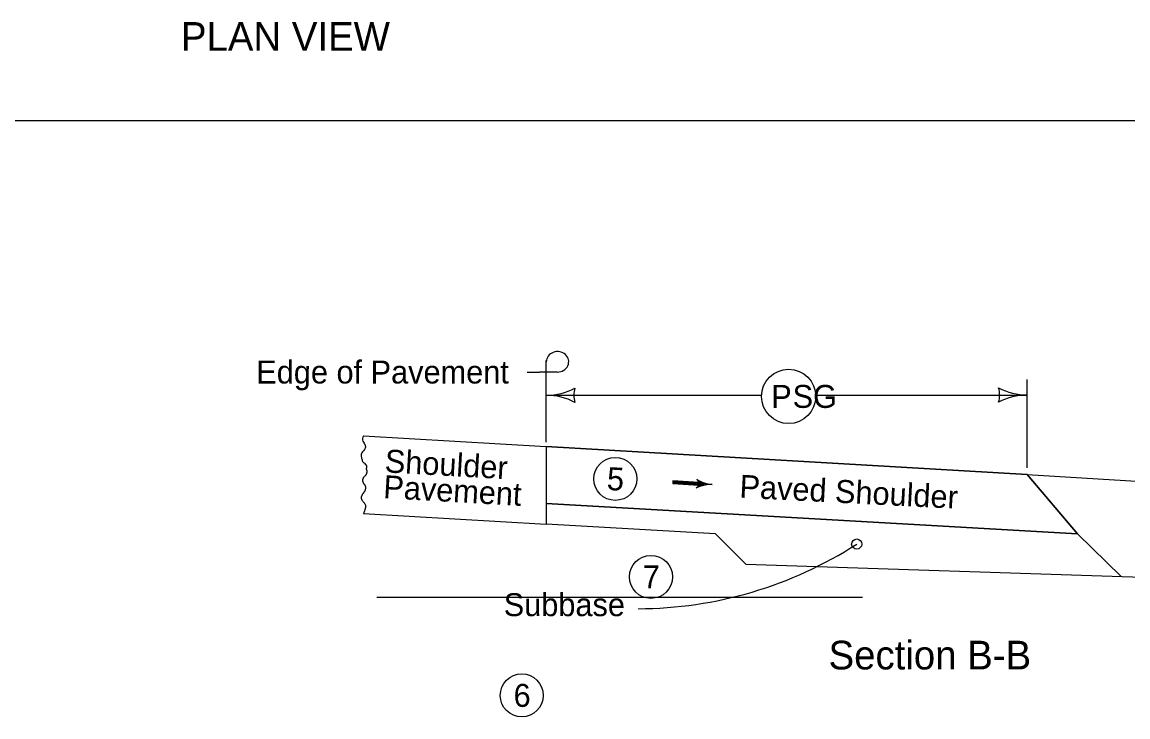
# Model space of a CAD drawing. Extents: x 10038 to 81668, y 7924 to 11018.
# Drawn here: x 11041 to 11812, y 8943 to 9428 of the extents above; entities that cross this region are included whole.
import ezdxf

# ---------------------------------------------------------------- set-up
doc = ezdxf.new("R2010")
doc.units = 0
for name, color, linetype in [('DsnShtMinorGrid05', 7, 'Continuous'), ('DsnShtMinorGrid09', 7, 'Continuous'), ('DsnShtMinorGrid10', 7, 'Continuous'), ('DsnShtMinorGrid11', 7, 'Continuous'), ('DsnShtMinorGrid14', 7, 'Continuous'), ('Level 60', 7, 'Continuous')]:
    doc.layers.add(name, color=color, linetype=linetype)

msp = doc.modelspace()

# ---------------------------------------------------------------- linework, layer by layer
at = {"layer": 'DsnShtMinorGrid05'}
for p, q in [((11742.05, 9116.81), (11742.05, 9178.49)), ((11406.83, 9167.5), (11556.83, 9167.5)), ((11594.65, 9167.65), (11742.05, 9167.65))]:
    msp.add_line(p, q, dxfattribs=at)
msp.add_circle((11575.74, 9166.68), 18.93, dxfattribs=at)
for centre, radius, start, end in [((11406.83, 9210), 42.5, 270, 298.07249), ((11442.47, 9167.5), 16.42, 162.26665, 197.73335), ((11706.41, 9167.65), 16.42, 342.26665, 17.73335), ((11742.05, 9210.15), 42.5, 241.92751, 270), ((11406.83, 9125), 42.5, 61.92751, 90), ((11742.05, 9125.15), 42.5, 90, 118.07249), ((11470.24, 9300.72), 282.03, 270.13198, 302.84273)]:
    msp.add_arc(centre, radius, start, end, dxfattribs=at)
at = {"layer": 'DsnShtMinorGrid09'}
for centre in [(11454.95, 9109.17), (11479.8, 9040.88), (11389.74, 8958.27)]:
    msp.add_circle(centre, 15, dxfattribs=at)
at = {"layer": 'DsnShtMinorGrid10'}
for p, q in [((11406.83, 9170.82), (11406.83, 9191.68)), ((11393.46, 9183.67), (11402.14, 9183.67)), ((11414.64, 9183.67), (11402.14, 9183.67)), ((11406.83, 9134.88), (11406.83, 9170.82)), ((11513.21, 9105.78), (11495.01, 9106.83)), ((11513.11, 9104.84), (11513.11, 9104.84)), ((11513.23, 9106.79), (11513.23, 9106.79))]:
    msp.add_line(p, q, dxfattribs=at)
for points in [[(11513.24, 9106.72), (11495.07, 9107.77), (11494.94, 9105.89), (11513.11, 9104.84), (11513.16, 9106.45), (11495.29, 9107.55), (11495.24, 9106.05), (11512.73, 9105.1), (11512.85, 9106.22), (11495.53, 9107.28), (11495.5, 9106.28), (11512.51, 9105.3), (11512.61, 9106.01), (11495.72, 9107.06), (11495.7, 9106.5), (11512.3, 9105.56)], [(11512.84, 9107.97), (11513.53, 9106.81), (11513.51, 9105.16), (11512.75, 9103.76), (11515.5, 9104.63), (11518.7, 9105.28), (11519.6, 9105.42), (11517.35, 9105.96), (11514.13, 9107.19), (11513.18, 9107.73), (11513.31, 9104.21), (11518.25, 9105.43), (11513.61, 9107.01), (11513.63, 9104.59), (11517.03, 9105.52), (11514.03, 9106.38), (11513.79, 9105), (11515.95, 9105.5), (11514.37, 9106.01), (11514.23, 9105.35), (11515.02, 9105.51)]]:
    msp.add_lwpolyline(points, dxfattribs=at)
for centre, major_axis, start_param, end_param in [((11414.64, 9190.8), (-7.81, 0), 1.570796, 6.283185), ((11509.44, 9105.99), (3.88, 0), 5.202895, 7.237436), ((11521.72, 9085), (22.17, 0), 1.537172, 2.061295), ((11524.51, 9125.42), (-22.17, 0), 0.954258, 1.478381)]:
    msp.add_ellipse(centre, major_axis=major_axis, ratio=0.913811, start_param=start_param, end_param=end_param, dxfattribs=at)
at = {"layer": 'DsnShtMinorGrid11'}
msp.add_line((12305.9, 9358.71), (10150.33, 9358.71), dxfattribs=at)
at = {"layer": 'DsnShtMinorGrid14'}
msp.add_circle((11623.19, 9063.77), 3.54, dxfattribs=at)
at = {"layer": 'Level 60'}
for p, q in [((11279.36, 9139.15), (11406.83, 9131.74)), ((11406.83, 9131.74), (11406.83, 9077.73)), ((11406.83, 9131.74), (11741.97, 9112.25)), ((11741.97, 9112.25), (11406.83, 9131.74)), ((11406.83, 9131.74), (11406.83, 9092.14)), ((11741.97, 9112.25), (11777.01, 9070.8)), ((11741.97, 9112.25), (11876.8, 9103.86)), ((11777.01, 9070.8), (11741.97, 9112.25)), ((11777.01, 9070.8), (11406.83, 9092.14)), ((11406.83, 9092.14), (11777.01, 9070.8)), ((11279.4, 9085.14), (11406.83, 9077.73)), ((11524.67, 9070.93), (11406.83, 9077.73)), ((11524.67, 9070.93), (11546.01, 9049.72)), ((11777.01, 9070.8), (11807.53, 9041.17)), ((11546.01, 9049.72), (12029.35, 9033.93)), ((11288.78, 9026.82), (11627.28, 9026.82))]:
    msp.add_line(p, q, dxfattribs=at)
msp.add_circle((11454.95, 9109.17), 15, dxfattribs=at)
for points in [[(11279.36, 9139.15), (11278.86, 9135.55), (11279.9, 9134.04), (11280.77, 9131.75), (11280.16, 9129.69), (11278.26, 9127.31), (11277.74, 9125.41), (11278.26, 9123.12), (11279.12, 9120.74), (11280.16, 9120.03), (11281.55, 9117.49), (11281.54, 9116.65)], [(11279.58, 9099.54), (11279.79, 9099.79), (11279.99, 9100.05), (11280.34, 9100.61), (11280.62, 9101.2), (11280.73, 9101.51), (11280.83, 9101.82), (11280.97, 9102.44), (11281.02, 9103.06), (11280.97, 9103.65), (11280.91, 9103.93), (11280.87, 9104.06), (11280.83, 9104.19), (11280.62, 9104.57), (11280.33, 9104.93), (11280.04, 9105.3), (11279.79, 9105.7), (11279.65, 9105.98), (11279.51, 9106.26), (11279.25, 9106.84), (11279.05, 9107.4), (11278.97, 9107.7), (11278.92, 9107.99), (11278.91, 9108.12), (11278.91, 9108.25), (11279.06, 9109.02), (11279.27, 9109.54), (11279.53, 9110.05), (11279.97, 9110.69), (11280.49, 9111.23), (11281, 9111.78), (11281.23, 9112.09), (11281.43, 9112.43), (11281.64, 9112.9), (11281.8, 9113.38), (11281.9, 9113.85), (11281.93, 9114.09), (11281.94, 9114.21), (11281.95, 9114.33), (11281.91, 9114.84), (11281.76, 9115.35), (11281.71, 9115.48), (11281.65, 9115.6), (11281.6, 9115.73), (11281.58, 9115.86), (11281.54, 9116.65)], [(11279.58, 9099.54), (11279.36, 9099.31), (11279.11, 9099.07), (11278.88, 9098.83), (11278.7, 9098.56), (11278.56, 9098.28), (11278.42, 9097.99), (11278.16, 9097.42), (11278.04, 9097.14), (11277.95, 9096.85), (11277.88, 9096.56), (11277.85, 9096.41), (11277.83, 9096.26), (11277.84, 9095.75), (11277.97, 9095.23), (11278.18, 9094.71), (11278.44, 9094.2), (11278.88, 9093.57), (11279.4, 9093.02), (11279.91, 9092.47), (11280.14, 9092.17), (11280.34, 9091.83), (11280.75, 9090.88), (11280.85, 9090.41), (11280.86, 9089.93), (11280.83, 9089.64), (11280.78, 9089.35), (11280.73, 9089.06), (11280.66, 9088.78), (11280.34, 9087.63), (11280.16, 9087.02), (11279.97, 9086.42), (11279.75, 9085.83), (11279.62, 9085.54), (11279.48, 9085.26), (11279.4, 9085.14)]]:
    msp.add_spline(points, degree=3, dxfattribs=at)

# ---------------------------------------------------------------- texts
at = {"layer": 'DsnShtMinorGrid05'}
for s, p in [('P', (11563.62, 9158.68)), ('SG', (11578.53, 9158.68))]:
    msp.add_text(s, height=16, dxfattribs=at).set_placement(p)
at = {"layer": 'DsnShtMinorGrid09'}
msp.add_text('5', height=16, rotation=356.69973, dxfattribs=at).set_placement((11448.73, 9101.52))
for s, p in [('7', (11474.09, 9032.88)), ('6', (11384.04, 8950.27))]:
    msp.add_text(s, height=16, dxfattribs=at).set_placement(p)
at = {"layer": 'DsnShtMinorGrid10'}
for s, height, p in [('PLAN VIEW', 20, (11152.19, 9407.6)), ('Edge of Pavement', 16, (11204.7, 9175.67)), ('Subbase', 16, (11377.18, 9013.5)), ('Section B-B', 20, (11603.57, 8976.35))]:
    msp.add_text(s, height=height, dxfattribs=at).set_placement(p)
for s, rotation, p in [('Shoulder', 356.73462, (11293.96, 9113.81)), ('Pavement', 356.73462, (11292.94, 9095.84)), ('Paved Shoulder ', 357.0678, (11541.23, 9096.14))]:
    msp.add_text(s, height=16, rotation=rotation, dxfattribs=at).set_placement(p)

doc.saveas('drawing.dxf')
